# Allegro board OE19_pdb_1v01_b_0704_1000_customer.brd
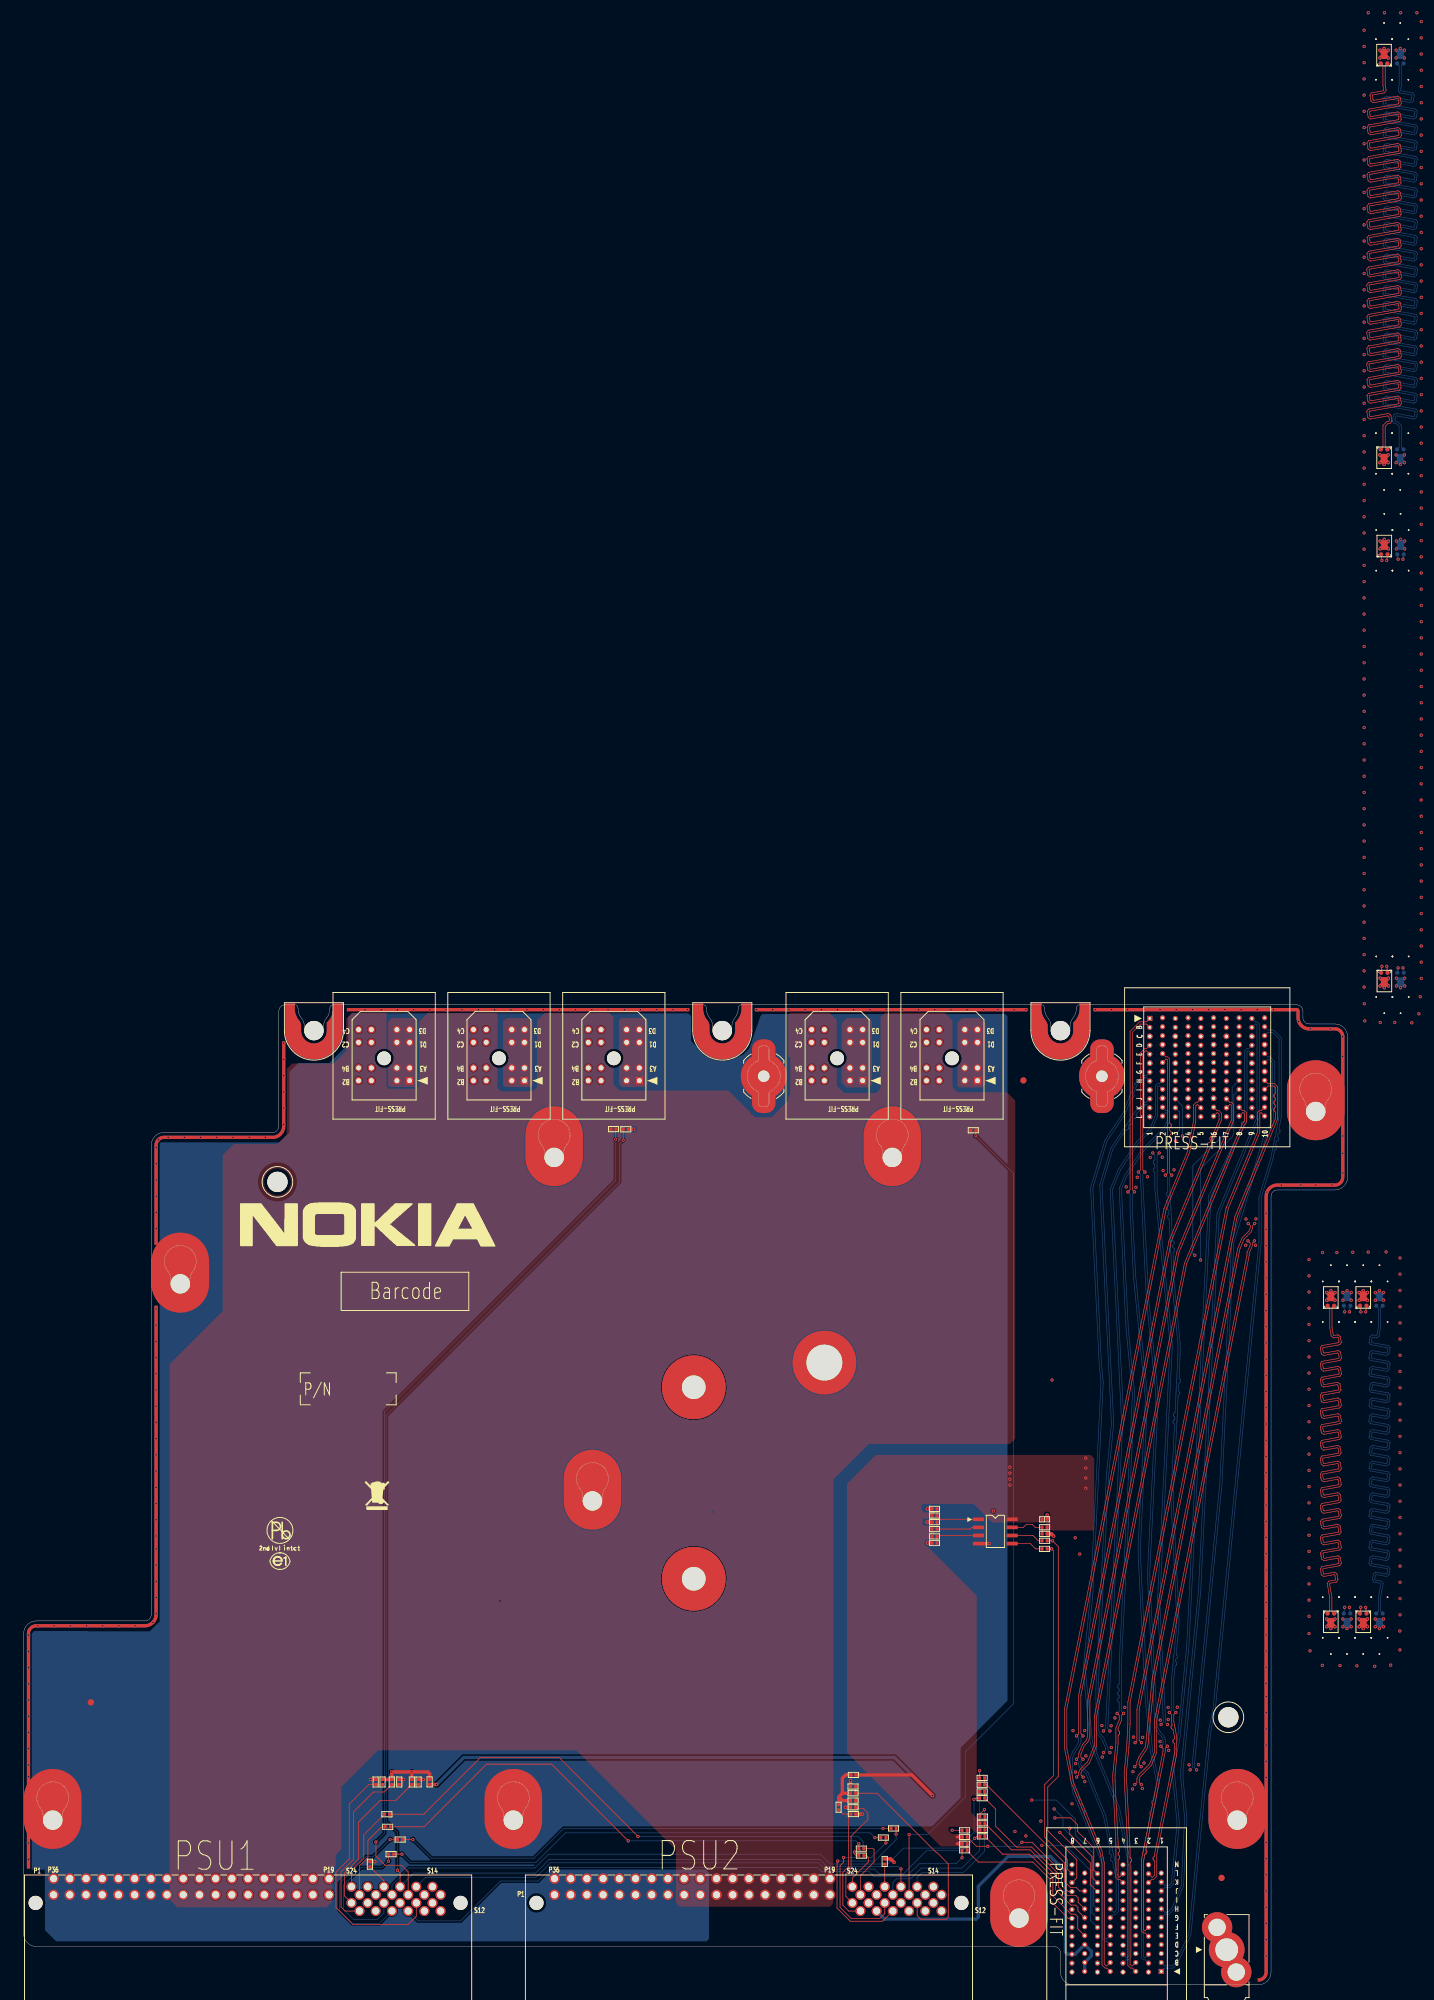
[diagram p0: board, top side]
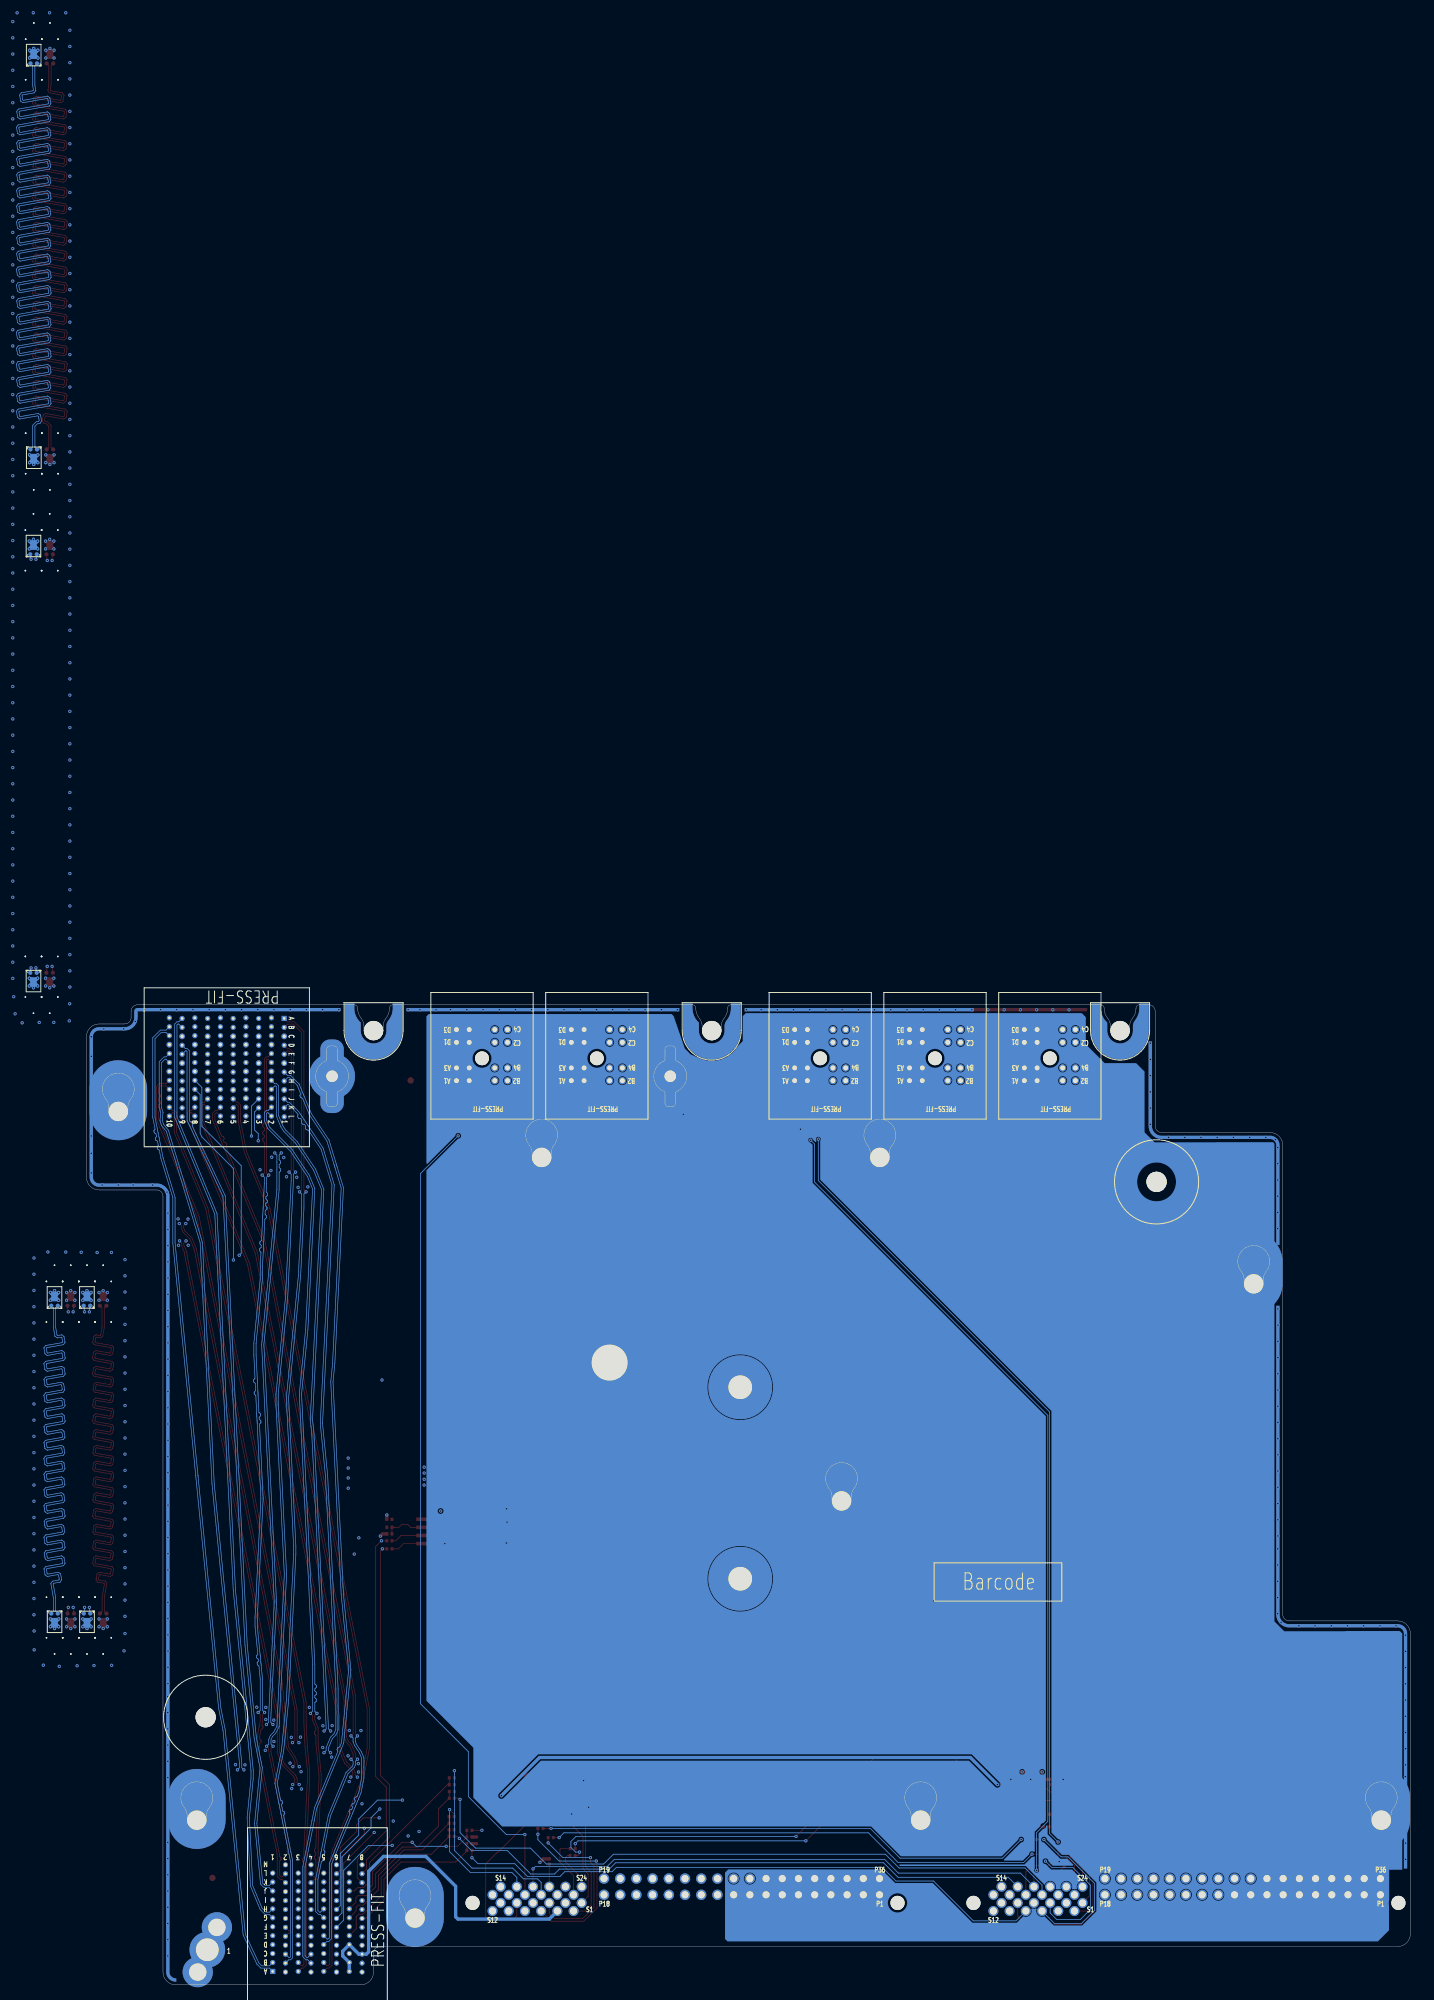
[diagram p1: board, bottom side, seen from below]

Outline 207.5 x 153.5 mm; copper layers: TOP, GND, IN1, VCC, VCC1, IN2, GND1, BOTTOM. Coordinates in mm from the lower left corner of the outline.

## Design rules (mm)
net group FRU_A2: nets FRU_A2 FRU_WP
net group SMB_PMBUS_SCL: nets SMB_PSU1_SCL SMB_PSU2_SCL
net group SMB_PMBUS_SDA: nets SMB_PSU1_SDA SMB_PSU2_SDA
net group SMB_PDB_FRU_SCL: nets SMB_PDB_FRU_SCL
net group SMB_PDB_FRU_SDA: nets SMB_PDB_FRU_SDA

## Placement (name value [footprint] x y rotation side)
C1046  0.1UF  [C0402]  160.02 72.91 0 top
DM2  -  [WEEE]  53.71 74.37 0 top
DM3  -  [PB-E1_SMALL]  40.18 71.17 0 top
DM4  -  [PNLABEL_15X5]  43.37 90.85 0 top
DM6  -  [PCB_VENDOR_LOGO_15X8]  108.07 74.12 0 top
DM7  -  [BARCODE_20X6]  74.63 60.1 180 bottom
DM8  -  [BARCODE_20X6]  49.77 105.61 0 top
H1  -  [HOLE_C9D3_5B9_OB3-5XC4-5_NPM_SPD]  202.5 136.8 180 top
H2  -  [HOLE_C9D3_5B9_OB3-5XC4-5_NPM_SPD]  136.15 129.6 180 top
H3  -  [HOLE_C9D3_5B9_OB3-5XC4-5_NPM_SPD]  83.15 129.6 180 top
H4  -  [HOLE_C9D3_5B9_OB3-5XC4-5_NPM_SPD]  156 10.46 180 top
H5  -  [HOLE_C9D3_5B9_OB3-5XC4-5_NPM_SPD]  89.15 75.8 180 top
H6  -  [HOLE_C9D3_5B9_OB3-5XC4-5_NPM_SPD]  76.75 25.8 180 top
H7  -  [HOLE_C9D3_5B9_OB3-5XC4-5_NPM_SPD]  4.56 25.8 180 top
H8  -  [HOLE_C9D3_5B9_OB3-5XC4-5_NPM_SPD]  24.56 109.8 180 top
H9  -  [HOLE_C10D5-6B10_NPB]  125.5 97.46 0 top
H10  -  [HOLE_C10D3-7B10_NPB]  105.03 93.6 0 top
H11  -  [HOLE_C10D3-7B10_NPB]  105.03 63.6 0 top
H12  -  [HOLE_C9D3B9N_CUTA_NPMXA]  162.5 149.46 180 top
H13  -  [HOLE_C9D3B9N_CUTA_NPMXA]  109.5 149.46 180 top
H14  -  [HOLE_C9D3B9N_CUTA_NPMXA]  45.5 149.46 180 top
H15  -  [HOLE_C9D3_5B9_OB3-5XC4-5_NPM_SPD]  190.2 25.8 180 top
H16  -  [HOLE_TOOLINGD125N_T2-0]  188.81 41.91 0 top
H17  -  [HOLE_TOOLINGD125N_T2-0]  39.78 125.76 0 top
J1  -  [HSD_F120D10_P2W1-4_RDH]  176.5 151.36 90 top
J2  -  [CON_PWR4X4H]  149.5 141.61 180 top
J3  -  [CON_PWR4X4H]  131.5 141.61 180 top
J4  -  [CON_PWR4X4H]  96.5 141.61 180 top
J5  -  [CON_PWR4X4H]  78.5 141.61 180 top
J6  -  [CON_GUIDE-M1XE]  116 142.31 0 top
J7  -  [CON_GUIDE-M1XE]  169 142.31 0 top
J8  -  [CON_GUIDE-M3XB]  188.55 5.5 0 top
J9  -  [HSD_F96D8H4D_P2W1-4_RDH]  178.3 2.1 180 top
J10  -  [CON_PWR4X4H]  60.5 141.62 180 top
J12  -  [TRIANG_LAUNCH_3PXA]  212.49 56.86 180 bottom
J13  -  [TRIANG_LAUNCH_3PXA]  209.95 56.86 0 top
J14  -  [TRIANG_LAUNCH_3PXA]  204.87 56.86 0 top
J15  -  [TRIANG_LAUNCH_3PXA]  207.41 56.86 180 bottom
J18  -  [TRIANG_LAUNCH_3PXA]  212.5 107.67 0 bottom
J19  -  [TRIANG_LAUNCH_3PXA]  209.95 107.67 180 top
J20  -  [TRIANG_LAUNCH_3PXA]  204.87 107.67 180 top
J21  -  [TRIANG_LAUNCH_3PXA]  207.42 107.67 0 bottom
J24  -  [TRIANG_LAUNCH_3PXA]  215.76 302.24 0 bottom
J25  -  [TRIANG_LAUNCH_3PXA]  213.25 225.35 180 top
J26  -  [TRIANG_LAUNCH_3PXA]  213.22 239.18 0 top
J27  -  [TRIANG_LAUNCH_3PXA]  215.8 225.35 0 bottom
J30  -  [TRIANG_LAUNCH_3PXA]  215.75 239.18 180 bottom
J31  -  [TRIANG_LAUNCH_3PXA]  213.26 157.22 0 top
J32  -  [TRIANG_LAUNCH_3PXA]  213.21 302.24 180 top
J33  -  [TRIANG_LAUNCH_3PXA]  215.79 157.22 180 bottom
JP1  -  [CON_F60D4H2D_P1-27W1-27_LDV]  51.38 12.83 270 top
JP2  -  [CON_F60D4H2D_P1-27W1-27_LDV]  129.88 12.83 270 top
NOREF  -  []  208.5 278.47 270 top
NOREF#2  -  []  190.2 25.8 0 top
NOREF#3  -  []  193.5 0 90 top
NOREF#4  -  []  76.75 25.8 0 top
NOREF#5  -  []  -1 76.52 90 top
NOREF#6  -  []  208.5 131.69 270 top
NOREF#7  -  []  27.22 134.5 0 top
NOREF#8  -  []  180.44 154.5 180 top
NOREF#9  -  [unnamed#2]  10.54 44.25 0 top
NOREF#10  -  []  -14.75 184.48 180 top
NOREF#11  -  []  -197.86 27.86 90 top
NOREF#12  -  []  181.65 164.48 180 top
NOREF#13  -  []  116 142.31 0 top
NOREF#14  -  []  -188.34 58 0 top
NOREF#15  -  []  19.31 154.5 180 top
NOREF#16  -  []  83.15 129.6 0 top
NOREF#17  -  []  9.16 58 0 top
NOREF#18  -  []  -198.5 111.83 90 top
NOREF#19  -  []  11 207.15 270 top
NOREF#20  -  []  -178.5 126.16 90 top
NOREF#21  -  []  11 225.14 270 top
NOREF#22  -  []  -63.56 164.48 0 top
NOREF#23  -  []  71.06 164.48 0 top
NOREF#24  -  []  208.5 225.14 270 top
NOREF#25  -  []  -197.49 44.96 90 top
NOREF#26  -  []  -171.65 154.5 0 top
NOREF#27  -  []  11 143.47 90 top
NOREF#28  -  []  -12.76 164.48 0 top
NOREF#29  -  []  11 242.46 270 top
NOREF#30  -  []  -199.5 0 0 top
NOREF#31  -  []  217.53 0 90 top
NOREF#32  -  []  -198.5 33.49 90 top
NOREF#33  -  []  109.5 149.46 0 top
NOREF#34  -  []  -186.5 204.14 90 top
NOREF#35  -  []  136.15 129.6 0 top
NOREF#36  -  []  -29 174.31 270 top
NOREF#37  -  []  19 93.71 90 top
NOREF#38  -  []  188.5 242.54 270 top
NOREF#39  -  []  -15.71 154.5 180 top
NOREF#40  -  []  19 111.74 90 top
NOREF#41  -  []  31.91 154.5 180 top
NOREF#42  -  []  5.1 195.48 180 top
NOREF#43  -  []  209.5 318.98 0 top
NOREF#44  -  []  -187.5 318.98 0 top
NOREF#45  -  []  11 273.84 270 top
NOREF#46  -  []  208.5 181.75 270 top
NOREF#47  -  []  4.9 123.5 0 top
NOREF#48  -  []  -178.5 111.74 90 top
NOREF#49  -  []  188.5 192.81 270 top
NOREF#50  -  []  198.34 260.98 180 top
NOREF#51  -  []  89.15 75.8 0 top
NOREF#52  -  []  -198.5 76.52 90 top
NOREF#53  -  []  -1 111.83 90 top
NOREF#54  -  []  -186.5 254.94 90 top
NOREF#55  -  []  196.5 64.93 270 top
NOREF#56  -  []  128.52 154.5 180 top
NOREF#57  -  []  188.55 5.5 0 top
NOREF#58  -  []  156 10.46 0 top
NOREF#59  -  []  -9 225.26 270 top
NOREF#60  -  []  -1 93.84 90 top
NOREF#61  -  []  24.56 109.8 0 top
NOREF#62  -  []  0 0 0 top
NOREF#63  -  []  4.56 25.8 0 top
NOREF#64  -  []  -180.82 436.99 0 top
NOREF#65  -  []  45.5 149.46 0 top
NOREF#66  -  []  -1 45.13 90 top
NOREF#67  -  []  188.55 5.5 0 top
NOREF#68  -  []  -186.5 229.54 90 top
NOREF#69  -  []  24.56 109.8 0 top
NOREF#70  -  []  -187.83 154.5 0 top
NOREF#71  -  []  -120.98 154.5 180 top
NOREF#72  -  []  188.5 207.23 270 top
NOREF#73  -  [unnamed#2]  156.69 141.66 0 top
NOREF#74  -  []  202.5 136.8 0 top
NOREF#75  -  []  188.5 225.26 270 top
NOREF#76  -  []  -67.63 154.5 180 top
NOREF#77  -  []  -178.5 93.71 90 top
NOREF#78  -  []  180.72 184.48 0 top
NOREF#79  -  []  75.18 154.5 180 top
NOREF#80  -  []  162.5 149.46 0 top
NOREF#81  -  []  196.5 36.16 270 top
NOREF#82  -  []  -198.5 137.23 90 top
NOREF#83  -  []  -1 20.59 90 top
NOREF#84  -  []  208.5 242.46 270 top
NOREF#85  -  []  136.15 129.6 0 top
NOREF#86  -  []  190.2 25.8 0 top
NOREF#87  -  []  208.5 207.15 270 top
NOREF#88  -  []  -12.76 164.48 0 top
NOREF#89  -  []  -9 242.54 270 top
NOREF#90  -  []  -198.5 93.84 90 top
NOREF#91  -  [unnamed#2]  187.74 16.75 0 top
NOREF#92  -  []  196.5 109.1 270 top
NOREF#93  -  []  169 142.31 0 top
NOREF#94  -  []  45.5 149.46 0 top
NOREF#95  -  []  0 8 0 top
NOREF#96  -  []  116 142.31 0 top
NOREF#97  -  []  -198.5 46.85 90 top
NOREF#98  -  []  169 142.31 0 top
NOREF#99  -  []  162.5 149.46 0 top
NOREF#100  -  []  89.15 75.8 0 top
NOREF#101  -  []  196.5 87.29 270 top
NOREF#102  -  []  197.83 164.48 180 top
NOREF#103  -  []  418.27 256.36 0 top
NOREF#104  -  []  -170.72 134.5 180 top
NOREF#105  -  []  25.34 164.48 0 top
NOREF#106  -  []  -186.5 280.34 90 top
NOREF#107  -  []  -178.5 76.44 90 top
NOREF#108  -  []  121.86 164.48 0 top
NOREF#109  -  []  156 10.46 0 top
NOREF#110  -  []  83.15 129.6 0 top
NOREF#111  -  []  19 76.44 90 top
NOREF#112  -  []  76.75 25.8 0 top
NOREF#113  -  []  -127.06 164.48 0 top
NOREF#114  -  []  11 298.38 270 top
NOREF#115  -  []  -207.5 316.98 0 top
NOREF#116  -  []  197.5 0 0 top
NOREF#117  -  []  -9 207.23 270 top
NOREF#118  -  []  0 0 0 top
NOREF#119  -  []  202.5 136.8 0 top
NOREF#120  -  []  -1 173.2 90 top
NOREF#121  -  []  4.56 25.8 0 top
NOREF#122  -  []  109.5 149.46 0 top
NOREF#123  -  []  -177.86 164.48 0 top
NOREF#124  -  []  0.84 260.98 180 top
R1  4.7K  [R0402]  127.73 27.82 270 top
R2  0  [R0402]  63.63 31.78 90 top
R3  4.7K  [R0402]  129.99 30.01 0 top
R4  0  [R0402]  130.04 32.87 180 top
R5  0  [R0402]  59.01 22.76 180 top
R6  0  [R0402]  134.74 23.07 0 top
R7  0  [R0402]  136.34 24.5 0 top
R8  0  [R0402]  57.07 24.75 0 top
R9  0  [R0402]  56.94 26.72 0 top
R10  0  [R0402]  131.29 21.33 180 top
R11  0  [R0402]  131.3 20.24 180 top
R12  0  [R0402]  150.23 29.24 0 top
R13  4.7K  [R0402]  57.7 31.77 270 top
R14  0  [R0402]  150.23 32.41 0 top
R15  4.7K  [R0402]  56.25 31.77 270 top
R16  0  [R0402]  150.26 23.26 0 top
R17  0  [R0402]  150.26 26.35 0 top
R18  0  [R0402]  147.47 21.07 0 top
R19  0  [R0402]  147.47 24.21 0 top
R21  1K  [R0402]  58.88 31.77 90 top
R23  4.7K  [R0402]  129.99 28.85 0 top
R24  1K  [R0402]  55.17 31.77 90 top
R25  1K  [R0402]  130 27.81 180 top
R26  0  [R0402]  92.44 134.03 0 top
R27  0  [R0402]  148.83 133.85 0 top
R28  4.7K  [R0402]  150.23 30.27 0 top
R29  4.7K  [R0402]  150.26 24.27 0 top
R30  4.7K  [R0402]  150.23 31.34 0 top
R31  4.7K  [R0402]  150.26 25.31 0 top
R32  0  [R0402]  94.38 134.01 0 top
R33  4.7K  [R0402]  147.47 22.1 0 top
R35  4.7K  [R0402]  147.47 23.16 0 top
R37  1K  [R0402]  130.04 26.74 0 top
R38  0  [R0402]  57.59 20.47 180 top
R39  1K  [R0402]  54.27 18.9 90 top
R40  1K  [R0402]  129.99 31.06 180 top
R41  1K  [R0402]  134.96 19.33 90 top
R324  100  [R0402]  142.75 69.2 180 top
R1112  4.7K  [R0402]  142.75 70.24 0 top
R1115  4.7K  [R0402]  142.75 71.38 0 top
R1116  100  [R0402]  142.75 72.46 180 top
R1118  4.7K  [R0402]  142.75 73.5 0 top
R1119  100  [R0402]  142.75 74.55 180 top
R1120  4.7K  [R0402]  160.02 71.67 180 top
R1121  100  [R0402]  160.02 70.63 0 top
R1126  33.2  [R0402]  160.02 69.55 0 top
R1127  33.2  [R0402]  160.02 68.29 0 top
R2297  4.7K  [R0402]  60.84 31.77 270 top
R2298  1K  [R0402]  61.91 31.77 90 top
U32  -  [SOIC8]  152.29 71.01 0 top

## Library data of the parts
C1046 = Q_CAP: alternate symbols: (C0402_OCTAGONXA); part number: Q_CAP_0402-0.1UF,25V,10%,X7R,CH4104K1B00; tolerance: 10%; signal model: DEFAULT_CAPACITOR_100000pF_2_1
DM2 = DUMMY_SYMBOL: part number: DUMMY_SYMBOL-WEEE,MECH,EMPTY,DUMMY2
DM3 = DUMMY_SYMBOL: part number: DUMMY_SYMBOL-PB-E1_SMALL,MECH,EMPTY,DUMMY3
DM4 = DUMMY_SYMBOL: part number: DUMMY_SYMBOL-PCBA_LABEL_15X5,MECH,MECH,DUMMY4
DM6 = DUMMY_SYMBOL: part number: DUMMY_SYMBOL-PCB_VENDOR_LOGO_15X8,MECH,EMPTY,DUMMY7
DM7 DM8 = DUMMY_SYMBOL: part number: DUMMY_SYMBOL-BARCODE_20X6,MECH,MECH,DUMMY15
H1-H8 H15 = HOLE: part number: HOLE_TH-EMPTY,HOLE1087
H9 = HOLE: part number: HOLE_TH-EMPTY,HOLE596
H10 H11 = HOLE: part number: HOLE_TH-EMPTY,HOLE974
H12-H14 = HOLE: part number: HOLE_TH-EMPTY,HOLE1057
H16 H17 = HOLE: part number: HOLE_TH-EMPTY,DUMMY50
J1 = CONN120_10130669102LF: part number: CONN120_10130669102LF-CONN120_10130669-102LF,THLF,IO,DFHSC0FS053
J2-J5 J10 = CONN16_100289164455P00LF: part number: CONN16_100289164455P00LF-CONN16_100289164455P00LF,THLF,IO,DFHS16FS012
J6 J7 = CONN1_D11402200000Z1: part number: CONN1_D11402200000Z1-CONN1_D11402-200000-Z1,THLF,EMPTY,DFHD01MS073
J8 = CONN3_D1141500000AZ1: part number: CONN3_D1141500000AZ1-CONN3_D11415-00000A-Z1,THLF,EMPTY,DFHD01MR025
J9 = CONN96_10133027101LF: part number: CONN96_10133027101LF-CONN96_10133027-101LF,THLF,IO,DFHS96FR004
J12-J15 J18-J21 J24-J27 J30-J33 = DELTA_L: part number: DELTA_L-DELTA-L,THLF,EMPTY,TP24
JP1 JP2 = CONN60_10147746001QLF: part number: CONN60_10147746001QLF-CONN60_10147746-001QLF,THLF,IO,DFHS24FR155
R1 R3 R13 R15 R23 R29 R31 R2297 = Q_RES: alternate symbols: (SMR0402AW); part number: Q_RES_0402LF-4.7K,1%,1/16W,EMPTY,CS24702FB10; tolerance: 1%
R2 R4 = Q_RES: alternate symbols: (SMR0402AW); part number: Q_RES_0402LF-0,5%,1/16W,EMPTY,CS00002JB38; tolerance: 5%
R5-R7 R12 R14 R16-R19 R26 R27 R32 R38 = Q_RES: alternate symbols: (SMR0402AW); part number: Q_RES_0402LF-0,5%,1/16W,CHIP,CS00002JB38; tolerance: 5%
R8-R11 = Q_RES: alternate symbols: (SMR0402AW); part number: Q_RES_0402LF-0,5%,1/16W,CHIP,CS00002JB38; tolerance: 5%; signal model: Q_RES_0402LF-0_5%_1/16W_CHIP_CA_0
R21 R24 R37 R39-R41 R2298 = Q_RES: alternate symbols: (SMR0402AW); part number: Q_RES_0402LF-1K,1%,1/16W,CHIP,TMP_QCS21002FB24; tolerance: 1%
R25 = Q_RES: alternate symbols: (SMR0402AW); part number: Q_RES_0402LF-1K,1%,1/16W,EMPTY,TMP_QCS21002FB24; tolerance: 1%
R28 R30 R33 R35 R1115 R1118 = Q_RES: alternate symbols: (SMR0402AW); part number: Q_RES_0402LF-4.7K,1%,1/16W,CHIP,CS24702FB10; tolerance: 1%
R324 R1121 = Q_RES: alternate symbols: (SMR0402AW); part number: Q_RES_0402LF-100,1%,1/16W,CHIP,TMP_QCS11002FB22; tolerance: 1%; signal model: DEFAULT_RESISTOR_100OHM_2_1
R1112 R1120 = Q_RES: alternate symbols: (SMR0402AW); part number: Q_RES_0402LF-4.7K,1%,1/16W,EMPTY,CS24702FB10; tolerance: 1%; signal model: DEFAULT_RESISTOR_4700OHM_2_1
R1116 R1119 = Q_RES: alternate symbols: (SMR0402AW); part number: Q_RES_0402LF-100,1%,1/16W,EMPTY,TMP_QCS11002FB22; tolerance: 1%
R1126 R1127 = Q_RES: alternate symbols: (SMR0402AW); part number: Q_RES_0402LF-33.2,1%,1/16W,CHIP,CS03322FB34; tolerance: 1%; signal model: Q_RES_0402LF-33.2_1%_1/16W_CHIA_33.2
U32 = M24M01RMN6TP: part number: M24M01RMN6TP-M24M01-RMN6TP,SMLF,IC,AKE35ZB0600

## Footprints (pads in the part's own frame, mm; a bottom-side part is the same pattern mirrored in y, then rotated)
BARCODE_20X6
  round 0.102 smd: 1(0,0)
C0402
  rect 0.457x0.508 smd: 1(-0.4,0) 2(0.4,0)
CON_F60D4H2D_P1-27W1-27_LDV
  round 2.21 hole 2.21 unplated: (0,17.1) (0,-49.5)
  round 1.626 hole 1.118: P1(-1.27,-46.68) P2(-1.27,-44.14) P3(-1.27,-41.6) P4(-1.27,-39.06) P5(-1.27,-36.52) P6(-1.27,-33.98) P7(-1.27,-31.44) P8(-1.27,-28.9) P9(-1.27,-26.36) P10(-1.27,-23.82) P11(-1.27,-21.28) P12(-1.27,-18.74) P13(-1.27,-16.2) P14(-1.27,-13.66) P15(-1.27,-11.12) P16(-1.27,-8.58) P17(-1.27,-6.04) P18(-1.27,-3.5) P19(-3.81,-3.5) P20(-3.81,-6.04) P21(-3.81,-8.58) P22(-3.81,-11.12) P23(-3.81,-13.66) P24(-3.81,-16.2) P25(-3.81,-18.74) P26(-3.81,-21.28) P27(-3.81,-23.82) P28(-3.81,-26.36) P29(-3.81,-28.9) P30(-3.81,-31.44) P31(-3.81,-33.98) P32(-3.81,-36.52) P33(-3.81,-39.06) P34(-3.81,-41.6) P35(-3.81,-44.14) P36(-3.81,-46.68)
  round 1.575 hole 1.118: S1(0,0) S2(1.27,1.27) S3(0,2.54) S4(1.27,3.81) S5(0,5.08) S6(1.27,6.35) S7(0,7.62) S8(1.27,8.89) S9(0,10.16) S10(1.27,11.43) S11(0,12.7) S12(1.27,13.97) S13(-1.27,13.97) S14(-2.54,12.7) S15(-1.27,11.43) S16(-2.54,10.16) S17(-1.27,8.89) S18(-2.54,7.62) S19(-1.27,6.35) S20(-2.54,5.08) S21(-1.27,3.81) S22(-2.54,2.54) S23(-1.27,1.27) S24(-2.54,0)
CON_GUIDE-M1XE
  custom 1.798x1.798 hole 5.182: G1(0,0)
CON_GUIDE-M3XB
  round 5.588 hole 3.556: 1(0,0)
  round 4.75 hole 2.718: 2(-1.5,3.5) 3(1.5,-3.5)
CON_PWR4X4H
  round 2.159 hole 2.159 unplated: (4,-3.5)
  rect 1.156x1.156 hole 0.75: A1(0,0)
  round 1.156 hole 0.75: A2(2,0) A3(0,-2) A4(2,-2) B1(6,0) B2(8,0) B3(6,-2) B4(8,-2) C1(6,-6) C2(8,-6) C3(6,-8) C4(8,-8) D1(0,-6) D2(2,-6) D3(0,-8) D4(2,-8)
HOLE_C9D3_5B9_OB3-5XC4-5_NPM_SPD
  oval 9.017x12.522 hole 3.023: 1(0,0)
HOLE_C9D3B9N_CUTA_NPMXA
  round 3.023 hole 3.023 unplated: (0,0)
HOLE_C10D3-7B10_NPB
  round 10.008 hole 3.708: 1(0,0)
HOLE_C10D5-6B10_NPB
  round 10.008 hole 5.613: 1(0,0)
HOLE_TOOLINGD125N_T2-0
  round 3.175 hole 3.175 unplated: (0,0)
HSD_F96D8H4D_P2W1-4_RDH
  rect 0.8x0.8 hole 0.4: A1(0,0)
  round 0.8 hole 0.5: A2(2,0.1) A4(6,0.1) A6(10,0.1) A8(14,0.1) C1(0,-2.8) C3(4,-2.8) C5(8,-2.8) C7(12,-2.8) D2(2,-4.1) D4(6,-4.1) D6(10,-4.1) D8(14,-4.1) F1(0,-7) F3(4,-7) F5(8,-7) F7(12,-7) G2(2,-8.3) G4(6,-8.3) G6(10,-8.3) G8(14,-8.3) I1(0,-11.2) I3(4,-11.2) I5(8,-11.2) I7(12,-11.2) J2(2,-12.5) J4(6,-12.5) J6(10,-12.5) J8(14,-12.5) L1(0,-15.4) L3(4,-15.4) L5(8,-15.4) L7(12,-15.4) M2(2,-16.7) M4(6,-16.7) M6(10,-16.7) M8(14,-16.7)
  round 0.8 hole 0.4: A3(4,0) A5(8,0) A7(12,0) B1(0,-1.4) B2(2,-1.3) B3(4,-1.4) B4(6,-1.3) B5(8,-1.4) B6(10,-1.3) B7(12,-1.4) B8(14,-1.3) C2(2,-2.7) C4(6,-2.7) C6(10,-2.7) C8(14,-2.7) D1(0,-4.2) D3(4,-4.2) D5(8,-4.2) D7(12,-4.2) E1(0,-5.6) E2(2,-5.5) E3(4,-5.6) E4(6,-5.5) E5(8,-5.6) E6(10,-5.5) E7(12,-5.6) E8(14,-5.5) F2(2,-6.9) F4(6,-6.9) F6(10,-6.9) F8(14,-6.9) G1(0,-8.4) G3(4,-8.4) G5(8,-8.4) G7(12,-8.4) H1(0,-9.8) H2(2,-9.7) H3(4,-9.8) H4(6,-9.7) H5(8,-9.8) H6(10,-9.7) H7(12,-9.8) H8(14,-9.7) I2(2,-11.1) I4(6,-11.1) I6(10,-11.1) I8(14,-11.1) J1(0,-12.6) J3(4,-12.6) J5(8,-12.6) J7(12,-12.6) K1(0,-14) K2(2,-13.9) K3(4,-14) K4(6,-13.9) K5(8,-14) K6(10,-13.9) K7(12,-14) K8(14,-13.9) L2(2,-15.3) L4(6,-15.3) L6(10,-15.3) L8(14,-15.3)
HSD_F120D10_P2W1-4_RDH
  rect 0.806x0.806 hole 0.4: A1(0,0)
  round 0.806 hole 0.4: A2(0.1,-2) A3(0,-4) A4(0.1,-6) A5(0,-8) A6(0.1,-10) A7(0,-12) A8(0.1,-14) A9(0,-16) A10(0.1,-18) B1(-1.4,0) B2(-1.3,-2) B3(-1.4,-4) B4(-1.3,-6) B5(-1.4,-8) B6(-1.3,-10) B7(-1.4,-12) B8(-1.3,-14) B9(-1.4,-16) B10(-1.3,-18) C2(-2.7,-2) C4(-2.7,-6) C6(-2.7,-10) C8(-2.7,-14) C10(-2.7,-18) D1(-4.2,0) D3(-4.2,-4) D5(-4.2,-8) D7(-4.2,-12) D9(-4.2,-16) E1(-5.6,0) E2(-5.5,-2) E3(-5.6,-4) E4(-5.5,-6) E5(-5.6,-8) E6(-5.5,-10) E7(-5.6,-12) E8(-5.5,-14) E9(-5.6,-16) E10(-5.5,-18) F2(-6.9,-2) F4(-6.9,-6) F6(-6.9,-10) F8(-6.9,-14) F10(-6.9,-18) G1(-8.4,0) G3(-8.4,-4) G5(-8.4,-8) G7(-8.4,-12) G9(-8.4,-16) H1(-9.8,0) H2(-9.7,-2) H3(-9.8,-4) H4(-9.7,-6) H5(-9.8,-8) H6(-9.7,-10) H7(-9.8,-12) H8(-9.7,-14) H9(-9.8,-16) H10(-9.7,-18) I2(-11.1,-2) I4(-11.1,-6) I6(-11.1,-10) I8(-11.1,-14) I10(-11.1,-18) J1(-12.6,0) J3(-12.6,-4) J5(-12.6,-8) J7(-12.6,-12) J9(-12.6,-16) K1(-14,0) K2(-13.9,-2) K3(-14,-4) K4(-13.9,-6) K5(-14,-8) K6(-13.9,-10) K7(-14,-12) K8(-13.9,-14) K9(-14,-16) K10(-13.9,-18) L1(-15.4,0) L2(-15.3,-2) L3(-15.4,-4) L4(-15.3,-6) L5(-15.4,-8) L6(-15.3,-10) L7(-15.4,-12) L8(-15.3,-14) L9(-15.4,-16) L10(-15.3,-18)
  round 0.906 hole 0.5: C1(-2.8,0) C3(-2.8,-4) C5(-2.8,-8) C7(-2.8,-12) C9(-2.8,-16) D2(-4.1,-2) D4(-4.1,-6) D6(-4.1,-10) D8(-4.1,-14) D10(-4.1,-18) F1(-7,0) F3(-7,-4) F5(-7,-8) F7(-7,-12) F9(-7,-16) G2(-8.3,-2) G4(-8.3,-6) G6(-8.3,-10) G8(-8.3,-14) G10(-8.3,-18) I1(-11.2,0) I3(-11.2,-4) I5(-11.2,-8) I7(-11.2,-12) I9(-11.2,-16) J2(-12.5,-2) J4(-12.5,-6) J6(-12.5,-10) J8(-12.5,-14) J10(-12.5,-18)
PB-E1_SMALL
  round 0.102 smd: 1(0,0)
PCB_VENDOR_LOGO_15X8
  round 0.102 smd: 1(0,0)
PNLABEL_15X5
  round 0.102 smd: 1(0,0)
R0402
  rect 0.457x0.508 smd: 1(-0.4,0) 2(0.4,0)
SOIC8
  rect 1.727x0.559 smd: 1(-2.642,1.905) 2(-2.642,0.635) 3(-2.642,-0.635) 4(-2.642,-1.905) 5(2.642,-1.905) 6(2.642,-0.635) 7(2.642,0.635) 8(2.642,1.905)
TRIANG_LAUNCH_3PXA
  round 0.254 hole 0.991 unplated: (-1.274,3.852) (-1.274,-2.498) (-0.004,-5.038) (1.266,3.852) (1.266,-2.498)
  round 0.66 smd: 1(-0.512,1.301) 2(0.504,1.301)
  rect 0.991x1.499 smd: 3(-0.004,-0.148)
unnamed#2
  round 0.991 smd: 1(0,0)
WEEE
  round 0.102 smd: 1(0,0)

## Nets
GND: C1046.2(B) H1.1 H2.1 H3.1 H4.1 H5.1 H6.1 H7.1 H8.1 H9.1 H15.1 J1.A2 J1.A4 J1.A6 J1.A8 J1.A10 J1.C1 J1.C3 J1.C5 J1.C7 J1.C9 J1.D2 J1.D4 J1.D6 J1.D8 J1.D10 J1.F1 J1.F3 J1.F5 J1.F7 J1.F9 J1.G2 J1.G4 J1.G6 J1.G8 J1.G10 J1.I1 J1.I3 J1.I5 J1.I7 J1.I9 J1.J2 J1.J4 J1.J6 J1.J8 J1.J10 J1.L1 J1.L3 J1.L5 J1.L7 J1.L9 J2.A1 J2.A2 J2.A3 J2.A4 J2.D1 J2.D2 J2.D3 J2.D4 J3.A1 J3.A2 J3.A3 J3.A4 J3.D1 J3.D2 J3.D3 J3.D4 J4.A1 J4.A2 J4.A3 J4.A4 J4.D1 J4.D2 J4.D3 J4.D4 J5.A1 J5.A2 J5.A3 J5.A4 J5.D1 J5.D2 J5.D3 J5.D4 J6.G1 J7.G1 J8.1 J8.2 J8.3 J9.A2 J9.A4 J9.A8 J9.C1 J9.C3 J9.C5 J9.C7 J9.D2 J9.D4 J9.D8 J9.F1 J9.F3 J9.F5 J9.F7 J9.G2 J9.G4 J9.I1 J9.I3 J9.I5 J9.I7 J9.J2 J9.J4 J9.L1 J9.L3 J9.L5 J9.M2 J9.M4 J9.M6 J9.M8 J10.A1 J10.A2 J10.A3 J10.A4 J10.D1 J10.D2 J10.D3 J10.D4 JP1.P1(P1_GND) JP1.P2(P2_GND) JP1.P3(P3_GND) JP1.P4(P4_GND) JP1.P5(P5_GND) JP1.P6(P6_GND) JP1.P7(P7_GND) JP1.P8(P8_GND) JP1.P9(P9_GND) JP1.P10(P10_GND) JP1.P29(P29_GND) JP1.P30(P30_GND) JP1.P31(P31_GND) JP1.P32(P32_GND) JP1.P33(P33_GND) JP1.P34(P34_GND) JP1.P35(P35_GND) JP1.P36(P36_GND) JP1.S10(S10_GND) JP1.S11(S11_GND) JP1.S12(S12_GND) JP1.S13(GND_S13) JP1.S14(GND_S14) JP1.S15(GND_S15) JP2.P1(P1_GND) JP2.P2(P2_GND) JP2.P3(P3_GND) JP2.P4(P4_GND) JP2.P5(P5_GND) JP2.P6(P6_GND) JP2.P7(P7_GND) JP2.P8(P8_GND) JP2.P9(P9_GND) JP2.P10(P10_GND) JP2.P29(P29_GND) JP2.P30(P30_GND) JP2.P31(P31_GND) JP2.P32(P32_GND) JP2.P33(P33_GND) JP2.P34(P34_GND) JP2.P35(P35_GND) JP2.P36(P36_GND) JP2.S10(S10_GND) JP2.S11(S11_GND) JP2.S12(S12_GND) JP2.S13(GND_S13) JP2.S14(GND_S14) JP2.S15(GND_S15) R21.2(B) R24.2(B) R25.2(B) R32.2(B) R37.2(B) R39.2(B) R40.2(B) R41.2(B) R324.2(B) R1116.2(B) R1119.2(B) R1121.2(B) R2298.2(B) U32.4(VSS)
P3V3_PSU1_ADDR: R2.2(B) R13.1(A) R15.1(A) R2297.1(A)
P3V3_PSU2_ADDR: R1.1(A) R3.1(A) R4.2(B) R23.1(A)
P3V3_RMC_STBY: C1046.1(A) J1.K4 J1.L4 J9.B8 R2.1(A) R4.1(A) R28.1(A) R29.1(A) R30.1(A) R31.1(A) R33.1(A) R35.1(A) R1112.1(A) R1115.1(A) R1118.1(A) R1120.1(A) U32.8(VCC)
P12V_PSU: J2.B1 J2.B2 J2.B3 J2.B4 J2.C1 J2.C2 J2.C3 J2.C4 J3.B1 J3.B2 J3.B3 J3.B4 J3.C1 J3.C2 J3.C3 J3.C4 J4.B1 J4.B2 J4.B3 J4.B4 J4.C1 J4.C2 J4.C3 J4.C4 J5.B1 J5.B2 J5.B3 J5.B4 J5.C1 J5.C2 J5.C3 J5.C4 J10.B1 J10.B2 J10.B3 J10.B4 J10.C1 J10.C2 J10.C3 J10.C4 JP1.P11(P11_V1) JP1.P12(P12_V1) JP1.P13(P13_V1) JP1.P14(P14_V1) JP1.P15(P15_V1) JP1.P16(P16_V1) JP1.P17(P17_V1) JP1.P18(P18_V1) JP1.P19(P19_V1) JP1.P20(P20_V1) JP1.P21(P21_V1) JP1.P22(P22_V1) JP1.P23(P23_V1) JP1.P24(P24_V1) JP1.P25(P25_V1) JP1.P26(P26_V1) JP1.P27(P27_V1) JP1.P28(P28_V1) JP2.P11(P11_V1) JP2.P12(P12_V1) JP2.P13(P13_V1) JP2.P14(P14_V1) JP2.P15(P15_V1) JP2.P16(P16_V1) JP2.P17(P17_V1) JP2.P18(P18_V1) JP2.P19(P19_V1) JP2.P20(P20_V1) JP2.P21(P21_V1) JP2.P22(P22_V1) JP2.P23(P23_V1) JP2.P24(P24_V1) JP2.P25(P25_V1) JP2.P26(P26_V1) JP2.P27(P27_V1) JP2.P28(P28_V1) R26.1(A) R27.1(A)
P12V_PSU_STBY: J9.A7 J9.B7 J9.C8 J9.D7 JP1.S3(S3_VSB) JP1.S4(S4_VSB) JP1.S21(VSB_S21) JP1.S22(VSB_S22) JP2.S3(S3_VSB) JP2.S4(S4_VSB) JP2.S21(VSB_S21) JP2.S22(VSB_S22)
DELTA_L_85_5INCH_BOT_DN: J12.1 J18.2
DELTA_L_85_5INCH_BOT_DP: J12.2 J18.1
DELTA_L_85_5INCH_IN1_DN: J15.1 J21.2
DELTA_L_85_5INCH_IN1_DP: J15.2 J21.1
DELTA_L_85_5INCH_IN2_DN: J13.1 J19.2
DELTA_L_85_5INCH_IN2_DP: J13.2 J19.1
DELTA_L_85_5INCH_TOP_DN: J14.1 J20.2
DELTA_L_85_5INCH_TOP_DP: J14.2 J20.1
DELTA_L_85_10INCH_BOT_DN: J24.1 J30.2
DELTA_L_85_10INCH_BOT_DP: J24.2 J30.1
DELTA_L_85_10INCH_IN1_DN: J27.1 J33.2
DELTA_L_85_10INCH_IN1_DP: J27.2 J33.1
DELTA_L_85_10INCH_IN2_DN: J25.1 J31.2
DELTA_L_85_10INCH_IN2_DP: J25.2 J31.1
DELTA_L_85_10INCH_TOP_DN: J26.1 J32.2
DELTA_L_85_10INCH_TOP_DP: J26.2 J32.1
FM_BBU_PRSNT_N: J1.B7 J9.I8
FM_BMC_SLED1_READY_N: J1.C8 J9.E6
FM_BMC_SLED2_READY_N: J1.H3 J9.F6
FM_BMC_SLED3_READY_N: J1.F8 J9.G6
FM_BMC_SLED4_READY_N: J1.K3 J9.H6
FM_BMC_SLED5_READY_N: J1.I8 J9.I6
FM_PSU1_PRSNT_N: J9.G8 R18.2(B) R33.2(B)
FM_PSU1_PRSNT_R_N: JP1.S8(S8_PRESENT_L) R18.1(A)
FM_PSU2_PRSNT_N: J9.J8 R19.2(B) R35.2(B)
FM_PSU2_PRSNT_R_N: JP2.S8(S8_PRESENT_L) R19.1(A)
FM_RMC_GPIO_0: J1.F6 J9.J6
FM_RMC_GPIO_1: J1.H6 J9.K6
FM_RMC_GPIO_2: J1.I6 J9.L6
FM_SLED1_PRSNT_N: J1.B8 J9.L7
FM_SLED2_PRSNT_N: J1.G3 J9.A6
FM_SLED3_PRSNT_N: J1.E8 J9.B6
FM_SLED4_PRSNT_N: J1.J3 J9.C6
FM_SLED5_PRSNT_N: J1.H8 J9.D6
FRU_A0: R1118.2(B) R1119.1(A) U32.1(DU)
FRU_A1: R1115.2(B) R1116.1(A) U32.2(E1)
FRU_A2: R324.1(A) R1112.2(B) U32.3(E2)
FRU_WP: R1120.2(B) R1121.1(A) U32.7(WC_N)
IRQ_PSU1_ALERT_N: J9.H7 R12.2(B) R28.2(B)
IRQ_PSU1_ALERT_R_N: JP1.S19(SMB_ALERT_L_S19) R12.1(A)
IRQ_PSU2_ALERT_N: J9.J7 R14.2(B) R30.2(B)
IRQ_PSU2_ALERT_R_N: JP2.S19(SMB_ALERT_L_S19) R14.1(A)
IRQ_RMC_ALERT_N: J1.E6 J9.K7
LAN_SLED1_MDIN0: J1.C10 J9.B1
LAN_SLED1_MDIN1: J1.E10 J9.E1
LAN_SLED1_MDIN2: J1.B9 J9.H1
LAN_SLED1_MDIN3: J1.E9 J9.J1
LAN_SLED1_MDIP0: J1.B10 J9.A1
LAN_SLED1_MDIP1: J1.F10 J9.D1
LAN_SLED1_MDIP2: J1.A9 J9.G1
LAN_SLED1_MDIP3: J1.D9 J9.K1
LAN_SLED2_MDIN0: J1.B1 J9.C2
LAN_SLED2_MDIN1: J1.E1 J9.F2
LAN_SLED2_MDIN2: J1.C2 J9.I2
LAN_SLED2_MDIN3: J1.F2 J9.L2
LAN_SLED2_MDIP0: J1.A1 J9.B2
LAN_SLED2_MDIP1: J1.D1 J9.E2
LAN_SLED2_MDIP2: J1.B2 J9.H2
LAN_SLED2_MDIP3: J1.E2 J9.K2
LAN_SLED3_MDIN0: J1.K10 J9.A3
LAN_SLED3_MDIN1: J1.H10 J9.E3
LAN_SLED3_MDIN2: J1.H9 J9.H3
LAN_SLED3_MDIN3: J1.J9 J9.J3
LAN_SLED3_MDIP0: J1.L10 J9.B3
LAN_SLED3_MDIP1: J1.I10 J9.D3
LAN_SLED3_MDIP2: J1.G9 J9.G3
LAN_SLED3_MDIP3: J1.K9 J9.K3
LAN_SLED4_MDIN0: J1.H1 J9.B4
LAN_SLED4_MDIN1: J1.K1 J9.E4
LAN_SLED4_MDIN2: J1.I2 J9.I4
LAN_SLED4_MDIN3: J1.L2 J9.K4
LAN_SLED4_MDIP0: J1.G1 J9.C4
LAN_SLED4_MDIP1: J1.J1 J9.F4
LAN_SLED4_MDIP2: J1.H2 J9.H4
LAN_SLED4_MDIP3: J1.K2 J9.L4
LAN_SLED5_MDIN0: J1.K5 J9.B5
LAN_SLED5_MDIN1: J1.K6 J9.E5
LAN_SLED5_MDIN2: J1.K7 J9.H5
LAN_SLED5_MDIN3: J1.L8 J9.K5
LAN_SLED5_MDIP0: J1.J5 J9.A5
LAN_SLED5_MDIP1: J1.L6 J9.D5
LAN_SLED5_MDIP2: J1.J7 J9.G5
LAN_SLED5_MDIP3: J1.K8 J9.J5
NC_PSU1_S7: JP1.S7(S7_RESERVED)
NC_PSU2_S7: JP2.S7(S7_RESERVED)
PD_PSU1_A0: JP1.S1(S1_A0) R2297.2(B) R2298.1(A)
PD_PSU1_A1: JP1.S2(S2_A1) R13.2(B) R21.1(A)
PD_PSU1_A2: JP1.S9(S9_A2) R15.2(B) R24.1(A)
PD_PSU1_PSON_N: JP1.S20(PSON_L_S20) R39.1(A)
PD_PSU2_A0: JP2.S1(S1_A0) R23.2(B) R25.1(A)
PD_PSU2_A1: JP2.S2(S2_A1) R1.2(B) R37.1(A)
PD_PSU2_A2: JP2.S9(S9_A2) R3.2(B) R40.1(A)
PD_PSU2_PSON_N: JP2.S20(PSON_L_S20) R41.1(A)
PSU1_HOTSTANDBYEN_H: JP1.S5(S5_HOTSTBYEN_H) R38.2(B)
PSU1_ISHARE: JP1.S6(S6_ISHARE) R5.2(B)
PSU1_REMOTE_SENSE_P: JP1.S17(V1_SENSE_S17) R26.2(B)
PSU2_HOTSTANDBYEN_H: JP2.S5(S5_HOTSTBYEN_H) R6.2(B)
PSU2_ISHARE: JP2.S6(S6_ISHARE) R7.2(B)
PSU2_REMOTE_SENSE_P: JP2.S17(V1_SENSE_S17) R27.2(B)
PSU_HOTSTANDBYEN_H: R6.1(A) R38.1(A)
PSU_ISHARE: R5.1(A) R7.1(A)
PSU_REMOTE_SENSE_R: JP1.S18(V1_SENSE_R_S18) JP2.S18(V1_SENSE_R_S18) R32.1(A)
PWR_PSU1_PWROK: J9.E7 R16.2(B) R29.2(B)
PWR_PSU1_PWROK_R: JP1.S16(PWOK_H_S16) R16.1(A)
PWR_PSU2_PWROK: J9.G7 R17.2(B) R31.2(B)
PWR_PSU2_PWROK_R: JP2.S16(PWOK_H_S16) R17.1(A)
SMB_BBU_ALERT_N: J1.A7 J9.H8
SMB_PDB_FRU_SCL: R1126.1(A) U32.6(SCL)
SMB_PDB_FRU_SDA: R1127.1(A) U32.5(SDA)
SMB_PMBUS_SCL: J1.D7 J9.E8 R8.2(B) R10.2(B)
SMB_PMBUS_SDA: J1.E7 J9.F8 R9.2(B) R11.2(B)
SMB_PSU1_SCL: JP1.S23(SCL_S23) R8.1(A)
SMB_PSU1_SDA: JP1.S24(SDA_S24) R9.1(A)
SMB_PSU2_SCL: JP2.S23(SCL_S23) R10.1(A)
SMB_PSU2_SDA: JP2.S24(SDA_S24) R11.1(A)
SMB_SLED_COMBINE_SCL: J1.G5 J9.K8 R1126.2(B)
SMB_SLED_COMBINE_SDA: J1.H5 J9.L8 R1127.2(B)
TGND: J12.3 J13.3 J14.3 J15.3 J18.3 J19.3 J20.3 J21.3 J24.3 J25.3 J26.3 J27.3 J30.3 J31.3 J32.3 J33.3

Pads without a net: DM2 1; DM3 1; DM4 1; DM6 1; DM7 1; DM8 1; H10 1; H11 1; J1 A3 A5 B3 B4 B5 B6 C4 C6 D3 D5 E3 E4 E5 F4 G7 H4 H7 I4; NOREF#9 1; NOREF#73 1; NOREF#91 1

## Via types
v1: diameter 0.508, hole 0.254, TOP to BOTTOM, 608 vias

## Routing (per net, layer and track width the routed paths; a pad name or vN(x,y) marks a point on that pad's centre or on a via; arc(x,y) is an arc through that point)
GND: length 13.8
  TOP w0.508: R2298.2 v1(62.62,32.17) ; R21.2 v1(59.52,32.17) ; R37.2 v1(131.45,26.74) ; R1121.2 161.09,70.63 v1(161.43,70.29) ; C1046.2 v1(160.42,73.59) ; R32.2 v1(95.6,134.01) ; v1(136.42,19.18) 135.88,19.73 R41.2 ; R324.2 v1(141.68,69.2) ; R24.2 v1(54.41,32.17) ; R39.2 v1(55.03,19.3) ; R40.2 v1(129.59,31.99) ; R25.2 v1(128.8,27.81) ; R1119.2 v1(141.65,74.55) ; R1116.2 v1(141.58,72.46) ; U32.4 v1(151.32,69.11)
  vias: v1(0.77,54.77) v1(0.77,52.23) v1(0.77,49.69) v1(0.77,47.15) v1(0.77,44.61) v1(0.77,42.07) v1(0.77,39.53) v1(0.77,36.99) v1(0.77,34.45) v1(0.79,32.61) v1(0.76,22.2) v1(0.76,19.66) v1(2.24,56.23) v1(4.78,56.23) v1(7.32,56.23) v1(9.86,56.23) v1(12.4,56.23) v1(14.94,56.23) v1(17.48,56.23) v1(20.27,56.76) v1(20.79,131.14) v1(20.79,128.6) v1(20.79,126.06) v1(20.79,123.52) v1(20.79,120.98) v1(20.79,118.44) v1(20.77,105.87) v1(20.77,103.33) v1(20.77,100.79) v1(20.77,98.25) v1(20.77,95.71) v1(20.77,93.17) v1(20.77,90.63) v1(20.77,88.09) v1(20.77,85.55) v1(20.77,83.01) v1(20.77,80.47) v1(20.77,77.93) v1(20.77,75.39) v1(20.77,72.85) v1(20.77,70.31) v1(20.79,68.29) v1(20.79,65.75) v1(20.79,63.21) v1(20.79,60.67) v1(20.79,58.13) v1(21.17,132.37) v1(22.65,132.72) v1(25.19,132.72) v1(27.73,132.72) v1(30.27,132.72) v1(32.81,132.72) v1(35.35,132.72) v1(37.89,132.72) v1(40.76,147.48) v1(40.76,144.94) v1(40.76,142.4) v1(40.76,139.86) v1(40.76,137.32) v1(40.76,134.78) v1(53.5,152.72) v1(56.04,152.72) v1(58.58,152.72) v1(61.12,152.72) v1(63.66,152.72) v1(66.2,152.72) v1(68.74,152.72) v1(71.28,152.72) v1(73.82,152.72) v1(76.36,152.72) v1(78.9,152.72) v1(81.44,152.72) v1(83.98,152.72) v1(86.52,152.72) v1(89.06,152.72) v1(91.6,152.72) v1(94.14,152.72) v1(96.68,152.72) v1(99.22,152.72) v1(101.76,152.72) v1(104.06,152.73) v1(114.86,152.73) v1(117.4,152.73) v1(119.94,152.73) v1(122.48,152.73) v1(125.02,152.73) v1(127.56,152.73) v1(130.1,152.73) v1(132.64,152.73) v1(135.18,152.73) v1(137.72,152.73) v1(140.26,152.73) v1(142.8,152.73) v1(145.34,152.73) v1(147.88,152.73) v1(150.42,152.73) v1(152.7,152.72) v1(155.24,152.72) v1(157.08,152.73) v1(164.47,39.82) v1(164.88,34.66) v1(164.85,33.33) v1(166.3,39.84) v1(166.31,31.84) v1(166.48,35.87) v1(167.94,152.73) v1(168.99,40.61) v1(169.07,35.67) v1(170.43,40.58) v1(170.48,152.73) v1(170.46,37.18) v1(171.03,41.81) v1(172.57,43.45) v1(172.8,124.98) v1(173.02,152.73) v1(173.79,30.67) v1(173.95,38.8) v1(173.86,33.39) v1(174.32,124.9) v1(174.54,126.49) v1(175.33,30.75) v1(175.38,38.76) v1(175.56,152.73) v1(175.58,34.73) v1(176.14,126.57) v1(176.57,129.58) v1(178.1,152.73) v1(178.14,41.46) v1(178.11,38.12) v1(178.46,129.62) v1(178.58,127.53) v1(179.38,43.45) v1(179.38,41.56) v1(179.46,36.72) v1(180.29,127.66) v1(180.64,152.73) v1(180.81,43.48) v1(182.66,34.46) v1(183.18,152.73) v1(184.13,34.49) v1(185.72,152.73) v1(188.26,152.73) v1(190.8,152.73) v1(191.54,115.83) v1(191.57,119.94) v1(193.13,119.97) v1(193.07,115.83) v1(193.34,152.73) v1(194.72,120.86) v1(194.72,118.32) v1(194.72,115.78) v1(194.72,113.24) v1(194.72,110.7) v1(194.72,108.16) v1(194.72,105.62) v1(194.72,103.08) v1(194.72,100.54) v1(194.72,98) v1(194.72,95.46) v1(194.72,92.92) v1(194.72,90.38) v1(194.72,87.84) v1(194.72,85.3) v1(194.72,82.76) v1(194.72,80.22) v1(194.72,77.68) v1(194.72,75.14) v1(194.72,72.6) v1(194.72,70.06) v1(194.72,67.52) v1(194.72,64.98) v1(194.72,62.44) v1(194.72,59.9) v1(194.72,57.36) v1(194.72,54.82) v1(194.72,52.28) v1(194.72,49.74) v1(194.72,47.2) v1(194.74,45.17) v1(194.74,42.63) v1(194.74,40.09) v1(194.74,37.55) v1(194.74,35.01) v1(194.74,32.47) v1(194.74,22.31) v1(194.74,19.77) v1(194.74,17.23) v1(194.74,14.69) v1(194.74,12.15) v1(194.74,9.61) v1(194.74,7.07) v1(194.74,4.53) v1(194.87,124.17) v1(195.88,152.73) v1(197.12,125.26) v1(198.42,152.73) v1(199.84,150.9) v1(200.18,125.28) v1(201.66,149.73) v1(202.51,125.26) v1(204.77,149.71) v1(205.03,125.26) v1(206.74,148.49) v1(206.74,145.43) v1(206.74,132.95) v1(206.74,130.24) v1(206.74,127.16)
P3V3_PSU1_ADDR: length 10.7
  TOP w0.508: R2297.1 v1(60.84,33.35) ; v1(60.84,33.35) 63.33,33.35 63.63,33.05 R2.2 ; v1(60.84,33.35) v1(57.71,33.35) 57.71,32.18 R13.1 R15.1
P3V3_PSU2_ADDR: length 9.2
  TOP w0.508: R4.2 128.83,32.87 128.32,32.37 128.32,30.01 ; 128.32,30.01 127.73,29.41 127.73,29.22 ; 128.32,30.01 R3.1 ; 127.73,29.22 127.98,29.22 128.35,28.85 R23.1 ; 127.73,29.22 R1.1
P3V3_RMC_STBY: length 136.4
  TOP w0.508: R4.1 139.21,32.87 v1(142.46,29.63) ; R35.1 146.33,23.16 ; R2.1 v1(64.73,31.38) ; R33.1 146.34,22.1
  IN1 w0.508: J9.B8 163.55,3.4 163.54,3.39 163.27,3.65 163.27,12.98 163.43,13.14 150.67,25.9 146.19,25.9 v1(142.46,29.63)
  BOTTOM w0.508: v1(64.73,31.38) 68.96,35.61 136.48,35.61 v1(142.46,29.63)
  vias: v1(151.99,74.21) v1(154.57,81.07) v1(154.57,80.15) v1(154.57,79.18) v1(154.58,78.27) v1(166.47,82.5) v1(166.47,80.94) v1(166.47,79.39) v1(166.47,77.78)
P12V_PSU_STBY: length 59.4
  BOTTOM w0.508: J9.A7 J9.B7 167.34,4.54 167.34,5.26 J9.D7 164.8,4.8 J9.C8 163.63,4.8 163.27,5.16 163.27,17.77 160.93,20.11 154.3,20.11 149.63,15.44 149.63,10.66 149.27,10.3 134.95,10.3 JP2.S4
DELTA_L_85_5INCH_BOT_DN: length 127
  BOTTOM w0.099: J12.1 212.67,58.49 212.67,60.57 213.07,62.87 212.83,63.22 211.83,63.4 211.75,63.51 211.87,64.17 211.98,64.25 213.63,63.96 213.98,64.21 214.15,65.15 213.9,65.51 211.3,65.97 211.22,66.08 211.34,66.74 211.45,66.82 213.6,66.44 213.95,66.69 214,67 214.03,67.16 214.06,67.32 214.12,67.63 213.87,67.99 211.3,68.44 211.22,68.55 211.33,69.21 211.45,69.29 213.64,68.9 214,69.15 214.16,70.09 213.92,70.45 211.34,70.9 211.26,71.02 211.37,71.68 211.49,71.76 213.61,71.38 213.96,71.63 214.02,71.94 214.05,72.1 214.07,72.27 214.13,72.57 213.88,72.93 211.29,73.39 211.21,73.5 211.33,74.16 211.44,74.24 213.64,73.85 213.99,74.1 214.05,74.41 214.05,74.41 214.08,74.57 214.1,74.73 214.16,75.04 213.91,75.4 211.33,75.85 211.25,75.97 211.36,76.62 211.48,76.7 213.64,76.32 213.99,76.57 214.16,77.51 213.91,77.87 211.32,78.33 211.24,78.44 211.35,79.1 211.47,79.18 213.64,78.8 213.99,79.04 214.05,79.35 214.08,79.51 214.08,79.51 214.11,79.68 214.16,79.99 213.91,80.34 211.31,80.8 211.23,80.92 211.34,81.57 211.46,81.65 213.65,81.27 214,81.51 214.17,82.46 213.92,82.81 211.33,83.27 211.25,83.38 211.37,84.04 211.48,84.12 213.64,83.74 213.99,83.99 214.04,84.3 214.07,84.46 214.1,84.63 214.16,84.93 213.91,85.29 211.31,85.75 211.23,85.86 211.34,86.52 211.46,86.6 213.63,86.21 213.98,86.46 214.04,86.77 214.04,86.77 214.07,86.93 214.1,87.1 214.15,87.41 213.9,87.76 211.28,88.22 211.2,88.34 211.32,89 211.43,89.08 213.64,88.69 214,88.93 214.05,89.24 214.08,89.41 214.11,89.57 214.16,89.88 213.91,90.23 211.3,90.69 211.22,90.81 211.34,91.46 211.45,91.55 213.65,91.16 214,91.41 214.17,92.35 213.92,92.7 211.36,93.16 211.28,93.27 211.39,93.93 211.51,94.01 213.64,93.63 213.99,93.88 214.16,94.82 213.91,95.18 211.28,95.64 211.2,95.76 211.31,96.41 211.43,96.49 213.65,96.1 214,96.35 214.17,97.29 213.92,97.65 211.27,98.12 211.19,98.23 211.31,98.89 211.42,98.97 213.64,98.58 213.99,98.83 214.16,99.77 213.91,100.12 211.3,100.58 211.22,100.7 211.34,101.35 211.45,101.44 212.08,101.33 212.43,101.57 212.67,102.95 212.67,106.04 J18.2
DELTA_L_85_5INCH_BOT_DP: length 127
  BOTTOM w0.099: J18.1 212.32,106.04 212.32,102.98 212.11,101.78 211.99,101.7 211.37,101.81 211.02,101.56 210.85,100.61 211.1,100.26 213.7,99.8 213.78,99.69 213.67,99.03 213.55,98.95 211.34,99.34 210.99,99.09 210.82,98.15 211.07,97.79 213.71,97.33 213.79,97.21 213.68,96.56 213.56,96.48 211.35,96.87 210.99,96.62 210.83,95.67 211.07,95.32 213.7,94.86 213.78,94.74 213.67,94.09 213.55,94.01 211.43,94.38 211.07,94.13 210.91,93.19 211.15,92.83 213.71,92.38 213.79,92.27 213.68,91.61 213.56,91.53 211.37,91.92 211.01,91.67 210.85,90.72 211.09,90.37 213.71,89.91 213.79,89.79 213.67,89.14 213.56,89.06 211.35,89.45 210.99,89.2 210.83,88.26 211.08,87.9 213.7,87.44 213.78,87.32 213.66,86.67 213.55,86.59 211.38,86.97 211.02,86.72 210.85,85.78 211.1,85.42 213.7,84.97 213.78,84.85 213.67,84.2 213.55,84.11 211.4,84.49 211.05,84.25 210.88,83.3 211.13,82.95 213.72,82.49 213.8,82.38 213.68,81.72 213.57,81.64 211.38,82.03 211.02,81.78 210.85,80.83 211.1,80.48 213.71,80.02 213.79,79.9 213.67,79.25 213.56,79.17 211.38,79.55 211.03,79.3 210.86,78.36 211.11,78 213.71,77.55 213.79,77.43 213.67,76.78 213.55,76.7 211.4,77.08 211.04,76.83 210.87,75.88 211.12,75.53 213.71,75.07 213.79,74.96 213.67,74.3 213.56,74.22 211.36,74.61 211,74.36 210.84,73.42 211.09,73.06 213.68,72.61 213.76,72.49 213.64,71.84 213.53,71.76 211.41,72.13 211.05,71.88 210.88,70.94 211.13,70.58 213.71,70.13 213.79,70.01 213.67,69.36 213.56,69.28 211.36,69.66 211.01,69.42 210.84,68.47 211.09,68.12 213.66,67.66 213.74,67.55 213.63,66.89 213.51,66.81 211.37,67.19 211.02,66.94 210.85,66 211.1,65.64 213.69,65.18 213.77,65.07 213.66,64.41 213.54,64.33 211.9,64.62 211.55,64.38 211.38,63.43 211.63,63.08 212.62,62.9 212.7,62.79 212.31,60.6 212.31,58.49 J12.2
DELTA_L_85_5INCH_IN1_DN: length 127
  IN1 w0.114: v1(207.79,59.12) 207.61,59.3 207.61,61.04 208.42,61.85 208.54,62.55 208.25,62.97 206.24,63.32 206.14,63.46 206.26,64.1 206.39,64.19 208.48,63.82 208.93,64.13 209.17,65.48 208.86,65.93 206.21,66.39 206.12,66.53 206.23,67.17 206.37,67.26 208.55,66.88 208.97,67.17 209.15,68.16 208.85,68.58 206.22,69.04 206.13,69.18 206.24,69.82 206.38,69.91 208.48,69.54 208.91,69.84 209.08,70.82 208.79,71.24 206.2,71.7 206.11,71.83 206.22,72.47 206.36,72.57 208.54,72.18 208.96,72.48 209.14,73.46 208.84,73.89 206.2,74.35 206.1,74.49 206.22,75.13 206.35,75.22 208.58,74.83 209,75.12 209.18,76.11 208.88,76.53 206.18,77.01 206.09,77.14 206.2,77.78 206.34,77.88 208.57,77.48 208.99,77.78 209.16,78.77 208.87,79.19 206.15,79.67 206.06,79.8 206.17,80.44 206.3,80.54 208.61,80.13 209.03,80.42 209.21,81.41 208.91,81.83 206.2,82.31 206.1,82.44 206.22,83.09 206.35,83.18 208.57,82.79 208.99,83.08 209.16,84.07 208.87,84.49 206.14,84.97 206.05,85.11 206.16,85.75 206.29,85.84 208.63,85.43 209.06,85.72 209.23,86.71 208.93,87.13 206.15,87.62 206.06,87.76 206.17,88.4 206.31,88.49 208.57,88.09 208.99,88.39 209.17,89.37 208.87,89.8 206.23,90.26 206.13,90.4 206.25,91.04 206.38,91.13 208.6,90.74 209.02,91.04 209.2,92.02 208.9,92.45 206.22,92.92 206.13,93.05 206.24,93.69 206.38,93.78 208.63,93.39 209.05,93.68 209.22,94.67 208.93,95.09 206.15,95.58 206.05,95.72 206.17,96.36 206.3,96.45 208.67,96.03 209.13,96.36 209.29,97.28 208.97,97.74 206.14,98.24 206.05,98.37 206.16,99.01 206.29,99.1 208.7,98.68 209.12,98.98 209.3,99.96 209,100.39 206.19,100.88 206.1,101.01 206.21,101.65 206.35,101.75 207.02,101.63 207.44,101.92 207.65,103.06 207.65,105.25 v1(207.8,105.41)
  BOTTOM w0.099: J15.1 v1(207.79,59.12) ; J21.2 v1(207.8,105.41)
DELTA_L_85_5INCH_IN1_DP: length 127
  IN1 w0.114: v1(207.04,105.41) 207.22,105.22 207.22,103.1 207.05,102.17 206.92,102.08 206.24,102.2 205.82,101.9 205.65,100.91 205.94,100.49 208.75,100 208.85,99.86 208.73,99.22 208.6,99.13 206.19,99.56 205.77,99.26 205.59,98.27 205.89,97.85 208.72,97.35 208.84,97.18 208.74,96.61 208.57,96.48 206.2,96.9 205.78,96.61 205.6,95.62 205.9,95.2 208.68,94.7 208.77,94.57 208.66,93.93 208.53,93.84 206.28,94.24 205.85,93.94 205.68,92.95 205.98,92.53 208.65,92.06 208.74,91.92 208.63,91.28 208.5,91.19 206.28,91.58 205.86,91.29 205.68,90.3 205.98,89.88 208.63,89.41 208.72,89.28 208.6,88.64 208.47,88.54 206.21,88.94 205.79,88.65 205.61,87.66 205.91,87.24 208.69,86.74 208.78,86.61 208.67,85.97 208.53,85.88 206.19,86.29 205.77,86 205.6,85.01 205.89,84.59 208.62,84.1 208.71,83.97 208.6,83.33 208.47,83.24 206.25,83.63 205.83,83.33 205.65,82.34 205.95,81.92 208.66,81.44 208.75,81.31 208.64,80.67 208.51,80.58 206.2,80.99 205.78,80.69 205.6,79.7 205.9,79.28 208.62,78.8 208.71,78.67 208.6,78.03 208.47,77.93 206.24,78.33 205.81,78.03 205.64,77.04 205.94,76.62 208.63,76.14 208.73,76.01 208.62,75.37 208.48,75.28 206.25,75.67 205.83,75.38 205.65,74.39 205.95,73.96 208.59,73.5 208.69,73.36 208.57,72.73 208.44,72.63 206.26,73.02 205.83,72.72 205.66,71.73 205.96,71.31 208.54,70.85 208.63,70.72 208.52,70.08 208.38,69.99 206.28,70.36 205.85,70.07 205.68,69.08 205.98,68.65 208.6,68.19 208.7,68.06 208.58,67.42 208.45,67.33 206.27,67.71 205.84,67.41 205.67,66.43 205.96,66 208.61,65.54 208.72,65.38 208.54,64.38 208.38,64.27 206.29,64.64 205.87,64.34 205.69,63.35 205.99,62.93 208,62.58 208.09,62.45 208.02,62.05 207.18,61.21 207.18,59.27 v1(207.03,59.12)
  BOTTOM w0.099: J21.1 v1(207.04,105.41) ; J15.2 v1(207.03,59.12)
DELTA_L_85_5INCH_IN2_DN: length 127
  TOP w0.099: J19.2 v1(209.58,105.41) ; J13.1 v1(209.57,59.12)
  IN2 w0.114: v1(209.57,59.12) 209.75,59.3 209.75,61.02 208.96,61.81 208.84,62.51 209.14,62.94 211.15,63.29 211.24,63.43 211.13,64.07 211,64.16 208.9,63.79 208.46,64.1 208.22,65.45 208.53,65.9 211.2,66.37 211.29,66.5 211.18,67.14 211.04,67.24 208.79,66.84 208.37,67.14 208.19,68.12 208.49,68.54 211.22,69.03 211.32,69.16 211.2,69.8 211.07,69.89 208.86,69.5 208.43,69.8 208.26,70.79 208.55,71.21 211.21,71.68 211.3,71.81 211.18,72.45 211.05,72.54 208.84,72.15 208.42,72.45 208.25,73.44 208.54,73.86 211.24,74.33 211.33,74.47 211.22,75.11 211.08,75.2 208.79,74.8 208.36,75.09 208.19,76.08 208.49,76.5 211.25,76.99 211.35,77.12 211.23,77.76 211.1,77.86 208.82,77.46 208.4,77.75 208.26,78.56 208.22,78.74 208.52,79.16 211.24,79.64 211.33,79.77 211.21,80.41 211.08,80.51 208.77,80.1 208.35,80.39 208.17,81.38 208.47,81.8 211.19,82.28 211.29,82.42 211.17,83.06 211.04,83.15 208.83,82.76 208.41,83.06 208.24,84.04 208.53,84.47 211.19,84.94 211.29,85.07 211.17,85.71 211.04,85.8 208.79,85.41 208.37,85.7 208.2,86.69 208.49,87.11 211.19,87.59 211.29,87.72 211.17,88.36 211.04,88.46 208.84,88.07 208.42,88.37 208.25,89.35 208.54,89.77 211.2,90.24 211.29,90.37 211.18,91.02 211.04,91.11 208.79,90.71 208.37,91.01 208.19,91.99 208.49,92.42 211.16,92.89 211.25,93.02 211.14,93.66 211.01,93.76 208.77,93.36 208.35,93.66 208.18,94.64 208.47,95.07 211.25,95.56 211.35,95.69 211.23,96.33 211.1,96.42 208.78,96.02 208.32,96.34 208.16,97.26 208.48,97.72 211.19,98.2 211.28,98.33 211.17,98.97 211.04,99.07 208.74,98.66 208.32,98.96 208.15,99.94 208.44,100.37 211.2,100.85 211.29,100.99 211.18,101.63 211.04,101.72 210.37,101.6 209.94,101.9 209.74,103.04 209.74,105.24 v1(209.58,105.41)
DELTA_L_85_5INCH_IN2_DP: length 127
  TOP w0.099: J13.2 v1(210.33,59.12) ; J19.1 v1(210.34,105.41)
  IN2 w0.114: v1(210.33,59.12) 210.17,59.28 210.17,61.2 209.36,62.01 209.29,62.41 209.39,62.55 211.23,62.87 211.4,62.91 211.7,63.33 211.52,64.32 211.1,64.61 209,64.24 208.85,64.35 208.67,65.35 208.78,65.51 211.44,65.98 211.74,66.4 211.57,67.39 211.14,67.69 208.89,67.29 208.75,67.38 208.64,68.02 208.73,68.15 211.47,68.64 211.77,69.06 211.59,70.05 211.17,70.35 208.96,69.96 208.82,70.05 208.71,70.69 208.8,70.82 211.45,71.29 211.75,71.71 211.57,72.7 211.15,72.99 208.94,72.61 208.81,72.7 208.7,73.34 208.79,73.47 211.49,73.95 211.78,74.37 211.64,75.18 211.61,75.36 211.19,75.65 208.89,75.25 208.75,75.34 208.64,75.98 208.73,76.11 211.5,76.6 211.8,77.02 211.65,77.84 211.62,78.01 211.2,78.31 208.92,77.91 208.79,78 208.68,78.64 208.77,78.77 211.48,79.25 211.78,79.67 211.63,80.49 211.6,80.66 211.18,80.96 208.87,80.55 208.73,80.64 208.62,81.28 208.72,81.41 211.44,81.89 211.74,82.32 211.56,83.31 211.14,83.6 208.93,83.21 208.8,83.31 208.69,83.94 208.78,84.08 211.44,84.55 211.74,84.97 211.56,85.96 211.14,86.26 208.89,85.86 208.76,85.95 208.65,86.59 208.74,86.72 211.44,87.2 211.74,87.62 211.56,88.61 211.14,88.91 208.94,88.52 208.81,88.61 208.7,89.25 208.79,89.38 211.44,89.85 211.74,90.27 211.57,91.26 211.14,91.56 208.89,91.16 208.76,91.26 208.64,91.89 208.74,92.03 211.41,92.5 211.71,92.92 211.53,93.91 211.11,94.21 208.87,93.81 208.74,93.91 208.63,94.54 208.72,94.68 211.5,95.17 211.8,95.59 211.62,96.58 211.2,96.88 208.89,96.47 208.71,96.59 208.61,97.16 208.73,97.33 211.44,97.81 211.73,98.23 211.56,99.22 211.14,99.52 208.84,99.11 208.71,99.21 208.6,99.84 208.69,99.98 211.44,100.46 211.74,100.89 211.56,101.87 211.14,102.17 210.47,102.05 210.33,102.14 210.17,103.07 210.17,105.24 v1(210.34,105.41)
DELTA_L_85_5INCH_TOP_DN: length 127
  TOP w0.099: J14.1 204.69,58.49 204.69,60.63 204.3,62.87 204.55,63.22 205.54,63.4 205.62,63.51 205.5,64.17 205.39,64.25 203.75,63.96 203.39,64.21 203.23,65.15 203.47,65.51 206.07,65.97 206.15,66.08 206.03,66.74 205.92,66.82 203.78,66.44 203.42,66.69 203.37,67 203.34,67.16 203.31,67.32 203.26,67.63 203.5,67.99 206.08,68.44 206.16,68.55 206.04,69.21 205.93,69.29 203.73,68.9 203.38,69.15 203.21,70.1 203.46,70.45 206.03,70.9 206.11,71.02 206,71.68 205.88,71.76 203.76,71.38 203.41,71.63 203.36,71.94 203.33,72.1 203.3,72.27 203.24,72.57 203.49,72.93 206.08,73.39 206.16,73.5 206.05,74.16 205.93,74.24 203.73,73.85 203.38,74.1 203.33,74.41 203.3,74.57 203.27,74.73 203.21,75.04 203.46,75.4 206.04,75.85 206.12,75.97 206.01,76.62 205.89,76.7 203.73,76.32 203.38,76.57 203.21,77.51 203.46,77.87 206.06,78.33 206.14,78.44 206.02,79.1 205.91,79.18 203.73,78.8 203.38,79.04 203.32,79.35 203.3,79.51 203.27,79.68 203.21,79.99 203.46,80.34 206.06,80.8 206.14,80.92 206.03,81.57 205.91,81.65 203.72,81.27 203.37,81.51 203.2,82.46 203.45,82.81 206.04,83.27 206.12,83.38 206,84.04 205.89,84.12 203.74,83.74 203.38,83.99 203.33,84.3 203.3,84.46 203.27,84.63 203.22,84.93 203.46,85.29 206.06,85.75 206.14,85.86 206.03,86.52 205.91,86.6 203.74,86.21 203.39,86.46 203.33,86.77 203.33,86.77 203.3,86.93 203.27,87.1 203.22,87.41 203.47,87.76 206.09,88.22 206.17,88.34 206.06,89 205.94,89.08 203.73,88.69 203.38,88.93 203.32,89.24 203.29,89.41 203.26,89.57 203.21,89.88 203.46,90.23 206.07,90.69 206.15,90.81 206.04,91.46 205.92,91.55 203.73,91.16 203.37,91.41 203.2,92.35 203.45,92.7 206.01,93.16 206.09,93.27 205.98,93.93 205.86,94.01 203.74,93.63 203.38,93.88 203.22,94.82 203.46,95.18 206.09,95.64 206.17,95.76 206.06,96.41 205.94,96.49 203.73,96.1 203.37,96.35 203.21,97.29 203.45,97.65 206.1,98.12 206.18,98.23 206.06,98.89 205.95,98.97 203.74,98.58 203.38,98.83 203.22,99.77 203.46,100.12 206.07,100.58 206.15,100.7 206.03,101.35 205.92,101.44 205.3,101.33 204.94,101.57 204.7,102.95 204.7,106.04 J20.2
DELTA_L_85_5INCH_TOP_DP: length 127
  TOP w0.099: J20.1 205.05,106.04 205.05,102.98 205.27,101.78 205.38,101.7 206,101.81 206.36,101.56 206.52,100.61 206.27,100.26 203.67,99.8 203.59,99.69 203.71,99.03 203.82,98.95 206.03,99.34 206.39,99.09 206.55,98.15 206.3,97.79 203.66,97.33 203.58,97.21 203.69,96.56 203.81,96.48 206.03,96.87 206.38,96.62 206.55,95.67 206.3,95.32 203.67,94.86 203.59,94.74 203.71,94.09 203.82,94.01 205.95,94.38 206.3,94.13 206.47,93.19 206.22,92.83 203.66,92.38 203.58,92.27 203.69,91.61 203.81,91.53 206.01,91.92 206.36,91.67 206.53,90.72 206.28,90.37 203.66,89.91 203.58,89.79 203.7,89.14 203.81,89.06 206.02,89.45 206.38,89.2 206.55,88.26 206.3,87.9 203.67,87.44 203.59,87.32 203.71,86.67 203.82,86.59 206,86.97 206.35,86.72 206.52,85.78 206.27,85.42 203.67,84.97 203.59,84.85 203.71,84.2 203.82,84.11 205.97,84.49 206.32,84.25 206.49,83.3 206.24,82.95 203.66,82.49 203.58,82.38 203.69,81.72 203.81,81.64 206,82.03 206.35,81.78 206.52,80.83 206.27,80.48 203.67,80.02 203.59,79.9 203.7,79.25 203.82,79.17 205.99,79.55 206.34,79.3 206.51,78.36 206.26,78 203.67,77.55 203.59,77.43 203.7,76.78 203.82,76.7 205.98,77.08 206.33,76.83 206.5,75.88 206.25,75.53 203.67,75.07 203.59,74.96 203.7,74.3 203.82,74.22 206.01,74.61 206.37,74.36 206.53,73.42 206.29,73.06 203.7,72.61 203.62,72.49 203.73,71.84 203.85,71.76 205.97,72.13 206.32,71.88 206.49,70.94 206.24,70.58 203.67,70.13 203.59,70.01 203.7,69.36 203.82,69.28 206.01,69.66 206.36,69.42 206.53,68.47 206.28,68.12 203.71,67.66 203.63,67.55 203.75,66.89 203.86,66.81 206,67.19 206.36,66.94 206.52,66 206.28,65.64 203.68,65.19 203.6,65.07 203.71,64.41 203.83,64.33 205.47,64.62 205.83,64.38 205.97,63.57 205.97,63.58 205.99,63.43 205.75,63.08 204.75,62.9 204.67,62.79 205.05,60.66 205.05,58.49 J14.2
DELTA_L_85_10INCH_BOT_DN: length 254
  BOTTOM w0.099: J24.1 215.58,300.61 215.58,297.54 215.43,296.69 215.68,296.33 217.51,296.01 217.59,295.9 217.48,295.24 217.36,295.16 213.58,295.83 213.23,295.58 213.06,294.63 213.31,294.28 217.97,293.46 218.05,293.34 217.94,292.69 217.82,292.61 213.59,293.35 213.23,293.1 213.07,292.16 213.32,291.81 218.01,290.98 218.09,290.86 217.97,290.21 217.86,290.13 213.58,290.88 213.23,290.63 213.06,289.69 213.31,289.33 217.98,288.51 218.06,288.4 217.94,287.74 217.83,287.66 213.57,288.41 213.22,288.16 213.05,287.22 213.3,286.86 217.98,286.04 218.07,285.92 217.95,285.27 217.83,285.19 213.61,285.93 213.26,285.68 213.09,284.74 213.34,284.38 217.97,283.57 218.05,283.45 217.94,282.79 217.82,282.71 213.6,283.46 213.25,283.21 213.08,282.27 213.33,281.91 217.99,281.09 218.07,280.98 217.95,280.32 217.84,280.24 213.56,280.99 213.2,280.75 213.04,279.8 213.29,279.45 217.99,278.62 218.07,278.5 217.95,277.85 217.84,277.77 213.59,278.52 213.24,278.27 213.07,277.32 213.32,276.97 218.01,276.14 218.09,276.03 217.98,275.37 217.86,275.29 213.59,276.04 213.23,275.8 213.07,274.85 213.31,274.5 217.97,273.68 218.05,273.56 217.94,272.9 217.82,272.82 213.59,273.57 213.24,273.32 213.07,272.38 213.32,272.02 217.99,271.2 218.07,271.09 217.95,270.43 217.84,270.35 213.59,271.1 213.23,270.85 213.07,269.91 213.32,269.55 218.02,268.72 218.1,268.61 217.99,267.95 217.87,267.87 213.54,268.63 213.19,268.39 213.02,267.44 213.27,267.09 218.02,266.25 218.1,266.14 217.98,265.48 217.87,265.4 213.55,266.16 213.19,265.91 213.02,264.97 213.27,264.61 217.98,263.78 218.06,263.67 217.94,263.01 217.83,262.93 213.55,263.69 213.19,263.44 213.03,262.5 213.27,262.14 218,261.31 218.08,261.19 217.96,260.54 217.85,260.46 213.56,261.21 213.21,260.96 213.04,260.02 213.29,259.67 218.03,258.83 218.11,258.72 217.99,258.06 217.88,257.98 213.59,258.74 213.23,258.49 213.07,257.54 213.31,257.19 218,256.36 218.08,256.25 218.03,255.92 218.03,255.92 217.97,255.59 217.85,255.51 213.55,256.27 213.2,256.02 213.03,255.08 213.28,254.72 218.03,253.88 218.11,253.77 218,253.11 217.88,253.03 213.57,253.79 213.21,253.55 213.05,252.6 213.29,252.25 217.99,251.42 218.07,251.31 217.95,250.65 217.84,250.57 213.6,251.32 213.24,251.07 213.08,250.12 213.33,249.77 217.98,248.95 218.06,248.83 217.95,248.18 217.83,248.1 213.56,248.85 213.2,248.6 213.04,247.66 213.29,247.3 218.01,246.47 218.09,246.36 217.98,245.7 217.86,245.62 215.05,246.11 214.69,245.87 214.53,244.92 214.77,244.57 215.17,244.5 215.57,244.1 215.57,240.81 J30.2
DELTA_L_85_10INCH_BOT_DP: length 254
  BOTTOM w0.099: J24.2 215.93,300.61 215.93,297.51 215.8,296.77 215.88,296.66 217.72,296.33 217.97,295.98 217.8,295.03 217.45,294.79 213.67,295.45 213.55,295.37 213.43,294.72 213.51,294.6 218.18,293.78 218.42,293.43 218.26,292.48 217.9,292.23 213.67,292.98 213.56,292.9 213.44,292.24 213.52,292.13 218.21,291.3 218.46,290.95 218.29,290 217.94,289.75 213.67,290.51 213.55,290.43 213.44,289.77 213.52,289.66 218.18,288.83 218.43,288.48 218.27,287.53 217.91,287.29 213.66,288.04 213.54,287.96 213.43,287.3 213.51,287.19 218.19,286.36 218.44,286.01 218.27,285.06 217.92,284.81 213.69,285.56 213.58,285.48 213.46,284.82 213.54,284.71 218.18,283.89 218.43,283.53 218.26,282.59 217.91,282.34 213.68,283.09 213.57,283.01 213.45,282.35 213.53,282.24 218.2,281.41 218.44,281.06 218.28,280.11 217.92,279.87 213.64,280.62 213.53,280.54 213.41,279.88 213.49,279.77 218.19,278.94 218.44,278.59 218.27,277.64 217.92,277.39 213.68,278.14 213.56,278.06 213.44,277.41 213.52,277.29 218.22,276.46 218.47,276.11 218.3,275.16 217.95,274.92 213.67,275.67 213.55,275.59 213.44,274.93 213.52,274.82 218.18,274 218.42,273.65 218.26,272.7 217.9,272.45 213.67,273.2 213.56,273.12 213.44,272.46 213.52,272.35 218.19,271.52 218.44,271.17 218.28,270.22 217.92,269.98 213.67,270.73 213.56,270.64 213.44,269.99 213.52,269.87 218.23,269.04 218.48,268.69 218.31,267.75 217.96,267.5 213.62,268.26 213.51,268.18 213.39,267.52 213.47,267.41 218.22,266.57 218.47,266.22 218.31,265.27 217.95,265.03 213.63,265.79 213.51,265.71 213.4,265.05 213.48,264.94 218.18,264.11 218.43,263.75 218.27,262.81 217.91,262.56 213.63,263.31 213.52,263.23 213.4,262.58 213.48,262.46 218.2,261.63 218.45,261.28 218.28,260.33 217.93,260.08 213.65,260.84 213.53,260.76 213.42,260.1 213.5,259.99 218.23,259.15 218.48,258.8 218.32,257.85 217.96,257.61 213.67,258.36 213.55,258.28 213.44,257.63 213.52,257.51 218.21,256.68 218.46,256.33 218.29,255.39 217.94,255.14 213.63,255.9 213.52,255.82 213.4,255.16 213.48,255.05 218.24,254.21 218.49,253.85 218.32,252.91 217.97,252.66 213.65,253.42 213.53,253.34 213.42,252.68 213.5,252.57 218.19,251.74 218.44,251.39 218.27,250.44 217.92,250.19 213.68,250.94 213.57,250.86 213.45,250.21 213.53,250.09 218.19,249.27 218.44,248.92 218.27,247.97 217.91,247.72 213.64,248.48 213.53,248.4 213.41,247.74 213.49,247.63 218.22,246.79 218.47,246.44 218.3,245.49 217.95,245.25 215.13,245.74 215.02,245.66 214.96,245.33 214.9,245.01 214.98,244.89 215.35,244.83 215.93,244.24 215.93,240.82 J30.1
